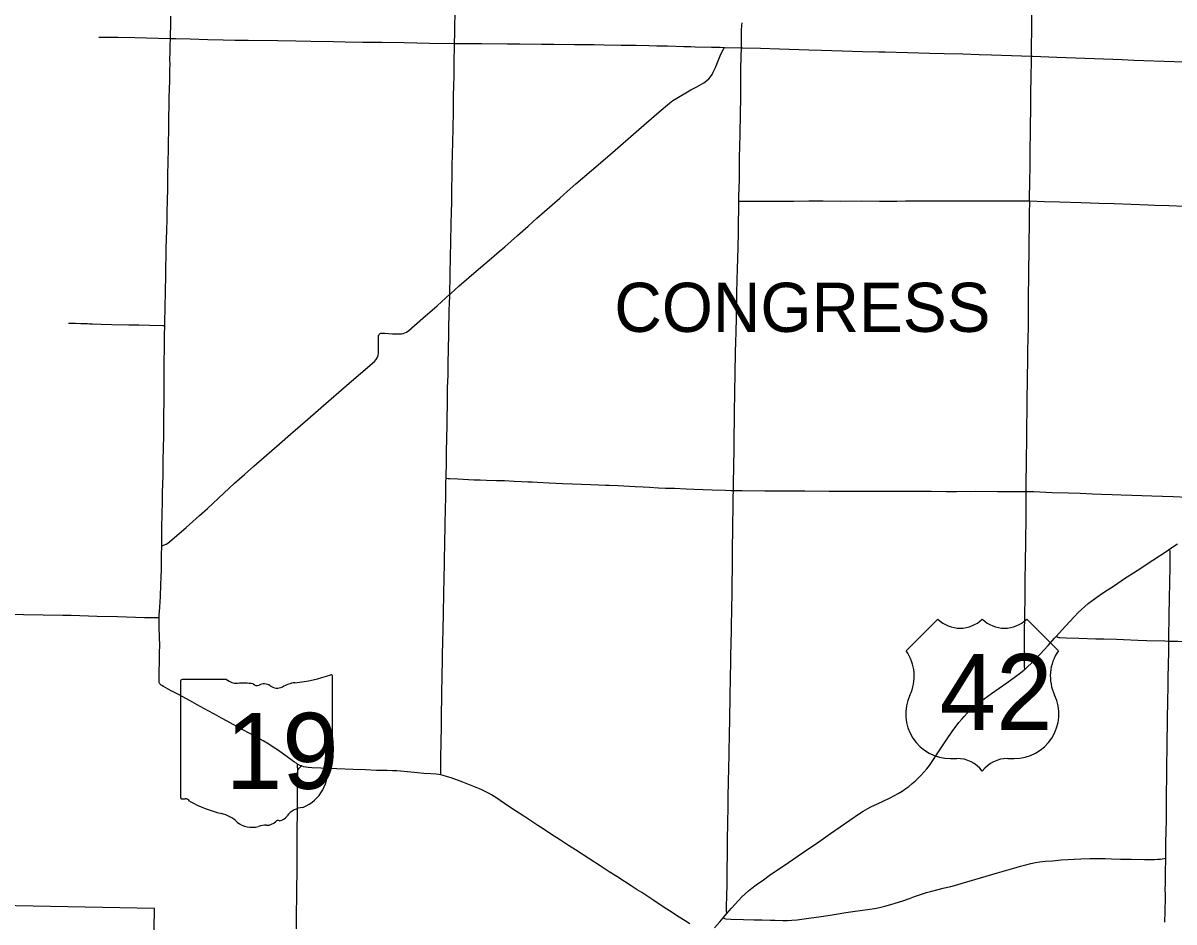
# Model space of a CAD drawing. Extents: x 1815539 to 1947826, y 273303 to 993194.
# Drawn here: x 1891996 to 1913070, y 939932 to 956396 of the extents above; entities that cross this region are included whole.
import ezdxf

# ---------------------------------------------------------------- set-up
doc = ezdxf.new("R2010")
doc.units = 0
for name, color, linetype in [('GM_X_County_Road', 7, 'Continuous'), ('GM_X_State_Route', 7, 'Continuous'), ('GM_X_Township', 7, 'Continuous'), ('GM_X_Township_Road', 7, 'Continuous'), ('GM_X_Township_Text', 7, 'Continuous'), ('GM_X_US_Route', 7, 'Continuous'), ('PV_X_Shoulder', 7, 'Continuous'), ('SC_Shading3', 7, 'Continuous')]:
    doc.layers.add(name, color=color, linetype=linetype)

msp = doc.modelspace()

# ---------------------------------------------------------------- linework, layer by layer
at = {"layer": 'GM_X_County_Road'}
for points in [[(1899898, 956020), (1899898, 956033), (1899900, 956197), (1899903, 956329), (1899908, 956575)], [(1905149, 955941), (1905149, 955972), (1905151, 956087), (1905154, 956267), (1905158, 956349), (1905163, 956398)], [(1899810, 951427), (1899814, 951568), (1899815, 951633), (1899817, 951764), (1899819, 951879), (1899822, 952027), (1899825, 952191), (1899827, 952305), (1899828, 952371), (1899830, 952436), (1899831, 952502), (1899835, 952600), (1899838, 952731), (1899841, 952911), (1899846, 953124), (1899849, 953269), (1899849, 953348), (1899849, 953396), (1899850, 953460), (1899851, 953509), (1899852, 953607), (1899853, 953722), (1899855, 953837), (1899858, 953935), (1899861, 954033), (1899864, 954180), (1899867, 954295), (1899870, 954377), (1899874, 954557), (1899877, 954688), (1899878, 954770), (1899879, 954918), (1899881, 955049), (1899885, 955262), (1899888, 955410), (1899891, 955640), (1899898, 956020)], [(1899810, 951427), (1899824, 951439), (1899984, 951580), (1900294, 951849), (1900531, 952051), (1900717, 952211), (1900816, 952297), (1901049, 952505), (1901246, 952678), (1901405, 952819), (1901823, 953189), (1901958, 953308), (1902119, 953449), (1902403, 953696), (1902740, 953984), (1903273, 954446), (1903643, 954771), (1903832, 954928), (1903897, 954977), (1903966, 955022), (1904222, 955169), (1904322, 955223), (1904378, 955252), (1904462, 955303), (1904516, 955341), (1904552, 955374), (1904584, 955411), (1904612, 955451), (1904635, 955494), (1904675, 955584), (1904723, 955706), (1904761, 955797), (1904804, 955885), (1904827, 955928), (1904839, 955950)], [(1899898, 956020), (1899947, 956020), (1900062, 956019), (1900390, 956018), (1900865, 956014), (1901095, 956012), (1901489, 956009), (1901718, 956008), (1902095, 956004), (1902456, 956001), (1902636, 955998), (1902948, 955993), (1903079, 955990), (1903128, 955989), (1903226, 955988), (1903455, 955983), (1903602, 955980), (1903684, 955979), (1903798, 955975), (1904093, 955967), (1904224, 955964), (1904306, 955962), (1904601, 955956), (1904666, 955954), (1904764, 955952), (1904839, 955950)], [(1904839, 955950), (1905149, 955941)], [(1905103, 953133), (1905105, 953218), (1905112, 953529), (1905115, 953693), (1905115, 953824), (1905118, 953923), (1905124, 954152), (1905125, 954333), (1905133, 954759), (1905137, 955005), (1905139, 955202), (1905142, 955563), (1905145, 955776), (1905149, 955941)], [(1905149, 955941), (1905174, 955941), (1905502, 955933), (1905846, 955923), (1906387, 955906), (1906616, 955898), (1906993, 955888), (1907370, 955877), (1907665, 955871), (1907780, 955869), (1908190, 955857), (1908599, 955845), (1908862, 955840), (1909206, 955831), (1909501, 955822), (1909730, 955815), (1910463, 955791)], [(1910427, 953140), (1910427, 953232), (1910430, 953446), (1910430, 953544), (1910435, 953725), (1910436, 953872), (1910437, 954003), (1910439, 954135), (1910442, 954332), (1910443, 954512), (1910447, 954824), (1910449, 955021), (1910451, 955152), (1910456, 955366), (1910462, 955743), (1910462, 955759), (1910463, 955791)], [(1910463, 955791), (1910484, 955790), (1910927, 955773), (1912123, 955726), (1912336, 955718), (1913073, 955691), (1913418, 955680), (1913598, 955675), (1913877, 955666), (1914254, 955655), (1914778, 955638), (1915384, 955619), (1915581, 955611), (1915640, 955608), (1915667, 955604), (1915693, 955599)], [(1905005, 947834), (1905005, 947856), (1905006, 948004), (1905009, 948233), (1905016, 948627), (1905019, 948840), (1905024, 949102), (1905026, 949283), (1905030, 949611), (1905031, 949709), (1905033, 949906), (1905036, 950070), (1905041, 950267), (1905044, 950398), (1905046, 950529), (1905052, 950759), (1905057, 950972), (1905060, 951136), (1905067, 951316), (1905069, 951464), (1905073, 951677), (1905078, 951906), (1905083, 952070), (1905094, 952529), (1905097, 952710), (1905101, 953021), (1905101, 953070), (1905103, 953133)], [(1910365, 947816), (1910365, 947932), (1910371, 948375), (1910376, 948802), (1910378, 949015), (1910383, 949294), (1910384, 949442), (1910384, 949606), (1910386, 949754), (1910390, 949951), (1910392, 950164), (1910397, 950394), (1910400, 950624), (1910404, 950820), (1910405, 951001), (1910406, 951132), (1910408, 951296), (1910409, 951477), (1910413, 951674), (1910414, 951887), (1910419, 952199), (1910419, 952396), (1910420, 952478), (1910422, 952609), (1910426, 952921), (1910428, 953117), (1910427, 953140)], [(1898523, 950700), (1898534, 950708), (1898549, 950714), (1898565, 950717), (1898615, 950716), (1898762, 950705), (1898894, 950701), (1898926, 950703), (1898959, 950708), (1898990, 950719), (1899019, 950734), (1899058, 950763), (1899318, 950990), (1899577, 951218), (1899736, 951361), (1899810, 951427)], [(1899743, 948058), (1899745, 948127), (1899750, 948307), (1899750, 948388), (1899753, 948553), (1899757, 948782), (1899762, 949045), (1899765, 949225), (1899767, 949340), (1899770, 949487), (1899770, 949651), (1899771, 949717), (1899778, 949946), (1899782, 950176), (1899786, 950405), (1899788, 950520), (1899790, 950602), (1899792, 950683), (1899794, 950798), (1899796, 950913), (1899797, 950978), (1899801, 951126), (1899806, 951273), (1899809, 951388), (1899810, 951427)], [(1894536, 946819), (1894587, 946839), (1894617, 946852), (1894645, 946869), (1894722, 946930), (1894983, 947156), (1895229, 947374), (1895374, 947507), (1895674, 947787), (1895867, 947966), (1896052, 948128), (1896224, 948280), (1896409, 948442), (1896695, 948690), (1896892, 948863), (1897029, 948981), (1897165, 949100), (1897451, 949346), (1897969, 949802), (1898429, 950199), (1898463, 950235), (1898481, 950262), (1898488, 950277), (1898498, 950308), (1898503, 950357), (1898504, 950554), (1898505, 950636), (1898508, 950669), (1898513, 950685), (1898522, 950698), (1898523, 950700)], [(1899644, 942628), (1899644, 942672), (1899645, 942770), (1899647, 942902), (1899647, 943000), (1899651, 943164), (1899653, 943295), (1899656, 943443), (1899659, 943557), (1899659, 943656), (1899659, 943721), (1899661, 943852), (1899663, 943934), (1899665, 944049), (1899667, 944164), (1899667, 944246), (1899668, 944311), (1899671, 944475), (1899676, 944688), (1899679, 944885), (1899682, 945000), (1899686, 945147), (1899687, 945196), (1899688, 945229), (1899691, 945326), (1899692, 945391), (1899693, 945473), (1899695, 945555), (1899696, 945637), (1899697, 945718), (1899699, 945816), (1899701, 945882), (1899703, 945997), (1899706, 946177), (1899708, 946275), (1899711, 946439), (1899712, 946537), (1899715, 946669), (1899717, 946767), (1899720, 946914), (1899722, 946980), (1899724, 947078), (1899725, 947210), (1899732, 947505), (1899735, 947701), (1899735, 947832), (1899736, 947882), (1899741, 947996), (1899742, 948045), (1899743, 948058)], [(1904886, 940090), (1904879, 940134), (1904879, 940200), (1904884, 940429), (1904887, 940593), (1904889, 940675), (1904891, 940773), (1904891, 940904), (1904892, 940970), (1904894, 941101), (1904895, 941314), (1904896, 941446), (1904898, 941560), (1904899, 941626), (1904902, 941806), (1904906, 941986), (1904909, 942183), (1904910, 942282), (1904913, 942445), (1904916, 942560), (1904921, 942691), (1904922, 942789), (1904924, 942953), (1904927, 943085), (1904931, 943331), (1904937, 943675), (1904944, 944036), (1904950, 944429), (1904956, 944675), (1904958, 944806), (1904966, 945265), (1904977, 945741), (1904978, 945872), (1904982, 946118), (1904987, 946430), (1904987, 946627), (1904989, 946823), (1904992, 947069), (1904994, 947250), (1904997, 947479), (1905002, 947709), (1905005, 947834)], [(1905005, 947834), (1905165, 947833), (1905576, 947830), (1905756, 947829), (1906002, 947828), (1906314, 947826), (1906757, 947824), (1907003, 947825), (1907216, 947824), (1907446, 947822), (1907643, 947823), (1907840, 947822), (1908184, 947822), (1908627, 947820), (1908906, 947819), (1909087, 947819), (1909431, 947820), (1909841, 947818), (1910055, 947817), (1910317, 947817), (1910365, 947816)], [(1910337, 944557), (1910335, 944618), (1910333, 944684), (1910333, 944782), (1910334, 945028), (1910336, 945208), (1910340, 945569), (1910343, 945865), (1910347, 946045), (1910346, 946242), (1910350, 946472), (1910355, 946931), (1910362, 947309), (1910363, 947506), (1910365, 947637), (1910365, 947816)], [(1910365, 947816), (1910498, 947813), (1910842, 947800), (1911137, 947790), (1911350, 947783), (1911580, 947775), (1911744, 947768), (1911941, 947760), (1912104, 947754), (1912301, 947748), (1912662, 947734), (1913055, 947722), (1913318, 947713), (1913597, 947703), (1913908, 947695), (1914023, 947692), (1914285, 947685), (1914367, 947681), (1914402, 947680)], [(1891793, 945572), (1892006, 945566), (1892728, 945552), (1892876, 945549), (1893352, 945535), (1893729, 945524), (1894221, 945511), (1894434, 945507), (1894492, 945506)]]:
    msp.add_lwpolyline(points, dxfattribs=at)
at = {"layer": 'GM_X_State_Route'}
msp.add_lwpolyline([(1904204, 939897), (1904123, 939952), (1904013, 940023), (1903832, 940137), (1903735, 940199), (1903544, 940325), (1903325, 940470), (1903242, 940523), (1903131, 940594), (1903008, 940675), (1902869, 940763), (1902731, 940852), (1902566, 940959), (1902374, 941085), (1902111, 941252), (1901987, 941333), (1901836, 941432), (1901657, 941548), (1901519, 941636), (1901424, 941700), (1901164, 941872), (1901012, 941970), (1900876, 942062), (1900671, 942198), (1900574, 942260), (1900517, 942293), (1900459, 942323), (1900384, 942357), (1900202, 942433), (1900049, 942492), (1899833, 942572), (1899771, 942593), (1899692, 942617), (1899644, 942628), (1899612, 942634), (1899563, 942639), (1899464, 942644), (1899333, 942652), (1899219, 942662), (1899039, 942681), (1898909, 942695), (1898843, 942700), (1898761, 942703), (1898663, 942705), (1898466, 942709), (1898269, 942716), (1898039, 942723), (1897744, 942736), (1897564, 942744), (1897449, 942748), (1897285, 942756), (1897220, 942761), (1897172, 942768), (1897140, 942774), (1897109, 942783), (1897093, 942789), (1897079, 942794), (1897035, 942816), (1897022, 942823), (1897007, 942832), (1896966, 942859), (1896859, 942936), (1896673, 943070), (1896578, 943135), (1896495, 943188), (1896396, 943247), (1896253, 943328), (1896022, 943453), (1895733, 943609), (1895633, 943664), (1895504, 943736), (1895389, 943800), (1895187, 943909), (1895058, 943980), (1894842, 944099), (1894711, 944167), (1894653, 944198), (1894566, 944245), (1894538, 944261), (1894525, 944270), (1894513, 944280), (1894504, 944292), (1894496, 944305), (1894491, 944320), (1894488, 944335), (1894487, 944351), (1894487, 944401), (1894489, 944532), (1894493, 944679), (1894498, 944876), (1894499, 944991), (1894496, 945155), (1894492, 945319), (1894491, 945434), (1894492, 945506), (1894492, 945548), (1894499, 945696), (1894511, 945892), (1894522, 946105), (1894528, 946253), (1894530, 946384), (1894533, 946647), (1894536, 946819), (1894536, 946827), (1894538, 946991), (1894540, 947188), (1894545, 947368), (1894550, 947664), (1894553, 947795), (1894560, 948107), (1894565, 948353), (1894570, 948648), (1894572, 948796), (1894573, 948960), (1894575, 949091), (1894576, 949255), (1894579, 949419), (1894579, 949583), (1894580, 949846), (1894580, 949944), (1894582, 950075), (1894582, 950141), (1894583, 950223), (1894587, 950403), (1894588, 950485), (1894589, 950584), (1894590, 950698), (1894593, 950829), (1894593, 950855), (1894595, 950961), (1894600, 951141), (1894605, 951519), (1894611, 951732), (1894614, 951912), (1894618, 952142), (1894620, 952273), (1894631, 952601), (1894636, 952798), (1894638, 952929), (1894645, 953356), (1894649, 953635), (1894654, 953831), (1894659, 954110), (1894662, 954242), (1894664, 954389), (1894665, 954504), (1894666, 954635), (1894668, 954734), (1894670, 954824), (1894670, 954865), (1894672, 954980), (1894675, 955045), (1894680, 955176), (1894684, 955340), (1894686, 955439), (1894687, 955537), (1894688, 955636), (1894688, 955668), (1894687, 955701), (1894687, 955783), (1894688, 955815), (1894689, 955864), (1894691, 955913), (1894692, 955978), (1894697, 956110), (1894697, 956114), (1894698, 956208), (1894700, 956323), (1894704, 956519)], dxfattribs=at)
at = {"layer": 'GM_X_Township'}
msp.add_lwpolyline([(1894363, 937552), (1894401, 940177), (1888046, 940302)], dxfattribs=at)
at = {"layer": 'GM_X_Township_Road'}
for points in [[(1910463, 955791), (1910464, 955947), (1910466, 956291), (1910467, 956587)], [(1893386, 956139), (1893534, 956138)], [(1893534, 956138), (1893731, 956136), (1894044, 956129), (1894472, 956121), (1894697, 956114)], [(1894697, 956114), (1894726, 956114), (1894792, 956113), (1895054, 956106), (1895382, 956094), (1895661, 956087), (1895875, 956084), (1896121, 956083), (1896662, 956074), (1896990, 956067), (1897269, 956061), (1897680, 956057), (1897893, 956054), (1898221, 956048), (1898566, 956042), (1898976, 956038), (1899436, 956028), (1899898, 956020)], [(1905103, 953133), (1905139, 953133), (1905401, 953134), (1905713, 953133), (1906107, 953136), (1906385, 953137), (1906648, 953137), (1906959, 953136), (1907353, 953137), (1907681, 953136), (1907993, 953136), (1908157, 953137), (1908337, 953138), (1908684, 953141)], [(1908684, 953141), (1908698, 953142), (1908944, 953139), (1909436, 953141), (1909912, 953142), (1910420, 953141), (1910427, 953140)], [(1910427, 953140), (1910699, 953130), (1910977, 953122), (1911371, 953109), (1911699, 953099), (1911977, 953091), (1912600, 953066), (1912715, 953060), (1912977, 953051), (1913551, 953030), (1913911, 953017), (1914354, 953002), (1914764, 952989), (1915010, 952982), (1915420, 952971), (1915633, 952967), (1915670, 952967)], [(1892832, 950898), (1892960, 950896), (1893057, 950894), (1893067, 950894)], [(1893067, 950894), (1893114, 950893), (1893165, 950891), (1893180, 950890), (1893212, 950888), (1893266, 950887), (1893425, 950881), (1893622, 950877), (1893934, 950871), (1894114, 950866), (1894311, 950861), (1894557, 950855), (1894593, 950855)], [(1899743, 948058), (1899780, 948054), (1899812, 948054), (1899960, 948046), (1900156, 948036), (1900254, 948032), (1900287, 948031), (1900369, 948029), (1900484, 948026), (1900663, 948020), (1900745, 948017), (1900811, 948015), (1900991, 948008), (1901123, 948001), (1901237, 947995), (1901319, 947991), (1901418, 947987), (1901631, 947976), (1901877, 947965), (1902057, 947957), (1902221, 947950), (1902385, 947946), (1902533, 947940), (1902664, 947935), (1902729, 947932), (1902893, 947923), (1903205, 947907), (1903352, 947900), (1903467, 947894), (1903631, 947886), (1903762, 947880), (1903926, 947874), (1904139, 947866), (1904287, 947860), (1904451, 947853), (1904615, 947847), (1904861, 947839), (1904959, 947835), (1905005, 947834)], [(1912974, 945078), (1912974, 945151), (1912981, 945528), (1912987, 945889), (1912992, 946118), (1912999, 946462), (1913000, 946659), (1912999, 946708), (1912994, 946763)], [(1910916, 945161), (1910960, 945145), (1910983, 945141), (1911096, 945136), (1911326, 945129), (1911638, 945120), (1911786, 945116), (1912016, 945110), (1912147, 945104), (1912410, 945096), (1912574, 945089), (1912903, 945081), (1912974, 945078)], [(1912919, 941100), (1912922, 941234), (1912924, 941349), (1912929, 941627), (1912931, 941758), (1912932, 941873), (1912934, 942070), (1912936, 942299), (1912940, 942578), (1912941, 942856), (1912943, 943070), (1912945, 943283), (1912950, 943529), (1912953, 943709), (1912957, 943922), (1912959, 944053), (1912961, 944168), (1912963, 944364), (1912971, 944692), (1912973, 944839), (1912974, 945036), (1912974, 945078)], [(1912974, 945078), (1913149, 945072), (1913510, 945059), (1913658, 945054), (1913773, 945051), (1914019, 945039), (1914200, 945032), (1914429, 945023), (1914544, 945019), (1914840, 945010), (1915021, 945002), (1915267, 944993), (1915382, 944987), (1915480, 944979), (1915529, 944973), (1915538, 944971)], [(1897001, 939804), (1897006, 940099), (1897010, 940378), (1897011, 940492), (1897011, 940640), (1897013, 940755), (1897017, 941033), (1897019, 941148), (1897018, 941328), (1897018, 941476), (1897019, 941656), (1897021, 941902), (1897022, 942050), (1897023, 942181), (1897023, 942279), (1897024, 942443), (1897027, 942657), (1897027, 942715)], [(1897027, 942715), (1897027, 942722), (1897025, 942771), (1897022, 942823)], [(1897027, 942715), (1897038, 942730), (1897055, 942751), (1897065, 942761), (1897093, 942789)], [(1904813, 940007), (1904840, 939996), (1904864, 939990), (1904958, 939986), (1905187, 939978), (1905384, 939974), (1905532, 939970), (1905680, 939966), (1905762, 939963), (1905909, 939960), (1905991, 939960), (1906073, 939963), (1906171, 939971), (1906383, 940000), (1906610, 940034), (1906773, 940057), (1906886, 940075), (1907064, 940106), (1907193, 940127), (1907323, 940145), (1907503, 940167), (1907584, 940180), (1907680, 940200), (1907776, 940223), (1907887, 940253), (1907965, 940276), (1908106, 940322), (1908230, 940365), (1908322, 940398), (1908447, 940440), (1908541, 940470), (1908635, 940498), (1908730, 940523), (1908841, 940551), (1908921, 940569), (1908985, 940584), (1909049, 940600), (1909175, 940635), (1909632, 940770), (1909836, 940831), (1910135, 940918), (1910261, 940955), (1910357, 940981), (1910452, 941003), (1910533, 941019), (1910614, 941032), (1910712, 941044), (1910843, 941055), (1911006, 941068), (1911367, 941087), (1911531, 941093), (1911662, 941094), (1911810, 941092), (1911925, 941090), (1912089, 941085), (1912285, 941082), (1912532, 941076), (1912646, 941075), (1912712, 941076), (1912777, 941080), (1912826, 941085), (1912919, 941100)], [(1912905, 939929), (1912911, 940123), (1912911, 940188), (1912912, 940317), (1912912, 940432), (1912911, 940533), (1912912, 940630), (1912913, 940697), (1912915, 940779), (1912916, 940892), (1912918, 941038), (1912919, 941100)]]:
    msp.add_lwpolyline(points, dxfattribs=at)
at = {"layer": 'GM_X_US_Route'}
for points in [[(1905097, 940327), (1905101, 940331), (1905158, 940390), (1905217, 940446), (1905278, 940500), (1905342, 940552), (1905420, 940611), (1905553, 940707), (1905661, 940781), (1906013, 941022), (1906284, 941208), (1906569, 941402), (1906783, 941553), (1906958, 941675), (1907310, 941917), (1907379, 941960), (1907463, 942010), (1907521, 942040), (1907639, 942098), (1907759, 942152), (1907863, 942201), (1907951, 942246), (1908022, 942286), (1908092, 942329), (1908160, 942375), (1908213, 942415), (1908277, 942466), (1908339, 942520), (1908387, 942565), (1908434, 942612), (1908489, 942673), (1908542, 942736), (1908592, 942801), (1908630, 942855), (1908757, 943046), (1908893, 943251), (1909022, 943441), (1909080, 943521), (1909130, 943585), (1909183, 943648), (1909227, 943696), (1909283, 943756), (1909341, 943813), (1909402, 943868), (1909465, 943921), (1909530, 943971), (1909729, 944115), (1910011, 944312), (1910171, 944427), (1910263, 944496), (1910327, 944548), (1910337, 944557), (1910389, 944602), (1910460, 944670), (1910542, 944751), (1910621, 944835), (1910764, 944993), (1910885, 945127), (1910916, 945161), (1911082, 945347), (1911247, 945529), (1911315, 945601), (1911374, 945657), (1911435, 945712), (1911498, 945765), (1911563, 945814), (1911656, 945881), (1911764, 945955), (1911997, 946108), (1912147, 946209), (1912394, 946372), (1912682, 946561), (1912944, 946730), (1912994, 946763), (1913136, 946855)], [(1904813, 940007), (1904886, 940090), (1904925, 940135), (1904969, 940184), (1905097, 940327)], [(1904656, 939827), (1904753, 939938), (1904813, 940007)]]:
    msp.add_lwpolyline(points, dxfattribs=at)
at = {"layer": 'PV_X_Shoulder'}
for p, q in [((1908748, 945479), (1908168, 944899)), ((1910953, 944899), (1910373, 945479)), ((1908980, 942927), (1909096, 942927)), ((1910025, 942927), (1910141, 942927))]:
    msp.add_line(p, q, dxfattribs=at)
for centre, radius, start, end in [((1909154, 945893), 580, 225.573, 314.427), ((1909967, 945893), 580, 225.573, 314.427), ((1907503, 944433), 812, 334.5471, 35.0009), ((1911618, 944433), 812, 144.9991, 205.4529), ((1908971, 943739), 812, 154.8319, 270.6383), ((1910150, 943739), 812, 269.3617, 25.1681), ((1909096, 942347), 580, 36.8699, 90), ((1910025, 942347), 580, 90, 143.1301)]:
    msp.add_arc(centre, radius, start, end, dxfattribs=at)
at = {"layer": 'SC_Shading3'}
for p, q in [((1894882, 944334), (1894882, 942221)), ((1895725, 944371), (1894909, 944371)), ((1897666, 943318), (1897666, 944423)), ((1897666, 943318), (1897666, 943318))]:
    msp.add_line(p, q, dxfattribs=at)
for centre, radius, start, end in [((1894914, 944339), 32.3, 98.1301, 188.1301), ((1895919, 944616), 313, 231.6195, 271.1119), ((1897051, 943725), 594, 97.3462, 120.7689), ((1896674, 947252), 2953, 275.8445, 288.9065), ((1897635, 944428), 31, 351.8621, 97.738), ((1896023, 943184), 1123, 80.4867, 94.9883), ((1896278, 944350), 90.3, 219.7921, 297.1024), ((1896410, 944106), 188, 54.4667, 119.1411), ((1896652, 944441), 226, 233.8562, 294.8282), ((1897659, 943236), 48, 107.944, 210.337), ((1897633, 943313), 33.2, 289.6038, 7.7341), ((1897354, 943097), 288, 340.033, 23.6496), ((1897777, 942855), 210, 136.8065, 186.9296), ((1896840, 942714), 739, 292.3089, 8.9858), ((1894914, 942216), 32.5, 171.9584, 258.3066), ((1894919, 942433), 248, 267.339, 280.6039), ((1894970, 942099), 89.5, 29.7484, 93.2717), ((1896100, 943998), 2132, 240.4129, 257.1985), ((1897151, 941628), 404, 94.4031, 142.5768), ((1895465, 941272), 667, 47.1842, 75.836), ((1896666, 941726), 63.5, 65.7517, 132.6484), ((1896639, 942016), 239, 282.8732, 323.2771), ((1896186, 942089), 423, 230.7004, 286.2918), ((1896431, 941358), 348, 85.6951, 111.2099), ((1896462, 941930), 226, 268.777, 315.5493)]:
    msp.add_arc(centre, radius, start, end, dxfattribs=at)

# ---------------------------------------------------------------- texts
at = {"layer": 'GM_X_Township_Text'}
msp.add_text('CONGRESS', height=900, rotation=0, dxfattribs=at).set_placement((1902823, 950739))
at = {"layer": 'PV_X_Shoulder'}
msp.add_text('42', height=1392.2, dxfattribs=at).set_placement((1908777, 943449))
at = {"layer": 'SC_Shading3'}
msp.add_text('19', height=1392.2, dxfattribs=at).set_placement((1895706, 942370))

doc.saveas('drawing.dxf')
